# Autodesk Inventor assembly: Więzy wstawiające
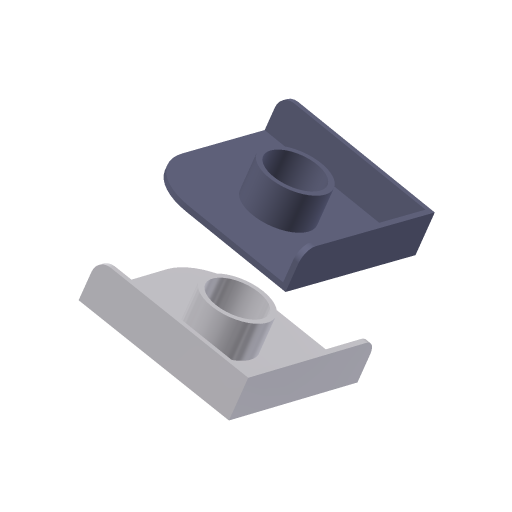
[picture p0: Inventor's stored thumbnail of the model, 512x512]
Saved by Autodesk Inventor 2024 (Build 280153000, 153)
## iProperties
Company: ATC
Created: 2023-03
Part Number: Więzy wstawiające
Document SubType Name: Assembly
Designer: Andrzej Jaskulski
Checked By: A.J.
Engr Approved By: Andrzej Jaskulski
Mfg Approved By: Andrzej Jaskulski
Authority: A.J.
Author: Andrzej Jaskulski
Title: A.J.: Kurs R2024-MEP
Revision Number: 1/24
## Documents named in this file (2)
- C:\Users\AndJas\Documents\R2024-MEP\Obszar roboczy\7-Zespół-Para-Więzy wstawiające.iam
- C:\Users\AndJas\Documents\R2024-MEP\Obszar roboczy\ss.ipt
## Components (2 placed, 1 different names)
1. ss:1
2. ss:2
